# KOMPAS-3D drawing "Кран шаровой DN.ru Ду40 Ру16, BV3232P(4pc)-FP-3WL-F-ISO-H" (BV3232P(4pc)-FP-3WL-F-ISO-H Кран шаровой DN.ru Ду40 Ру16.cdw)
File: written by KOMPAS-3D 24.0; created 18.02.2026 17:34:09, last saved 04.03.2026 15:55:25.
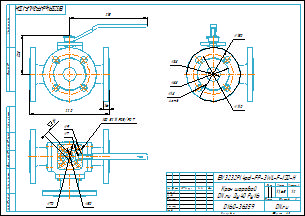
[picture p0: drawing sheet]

Document properties: Автор: R2D2; Форматы листов документа: A3; Полное имя файла: BV3232P(4pc)-FP-3WL-F-ISO-H Кран шаровой DN.ru Ду40 Ру16.m3d; Масса: 11.65; Наименование: Кран шаровой DN.ru Ду40 Ру16; Количество листов документа: 1; Примечание: D160-36359

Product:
- Part/product: Кран шаровой DN.ru Ду40 Ру16  | designation BV3232P(4pc)-FP-3WL-F-ISO-H
    Масса: 11.65
    Раздел спецификации: Прочие изделия
    Примечание: D160-36359

Views: Вид 1, Спереди, Проекционный вид 2
Referenced files in E:\Работа\Зайцев\BV3232P(4pc)-FP-3WL-F-ISO-H Кран шаровой DN.ru Ду15-100 Ру16\DN40\: BV3232P(4pc)-FP-3WL-F-ISO-H Кран шаровой DN.ru Ду40 Ру16.m3d
Referenced files in E:\Работа\Зайцев\Для компаса\: чертеж DN.ru А3.cdt
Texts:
  BV3232P(4pc)-FP-3WL-F-ISO-H
  чертеж DN.ru А3.cdt
  Кран шаровой
  DN.ru Ду40 Ру16
  Кран шаровой DN.ru Ду40 Ру16
  BV3232P(4pc)-FP-3WL-F-ISO-H Кран шаровой DN.ru Ду40 Ру16
Dimensions and other numbers on the sheet: 0; 3; 2; 4; 220; 16; 108; 215; 150; 110; 88; 18; 4 отв.; 38; 1:2; 1; 11,65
